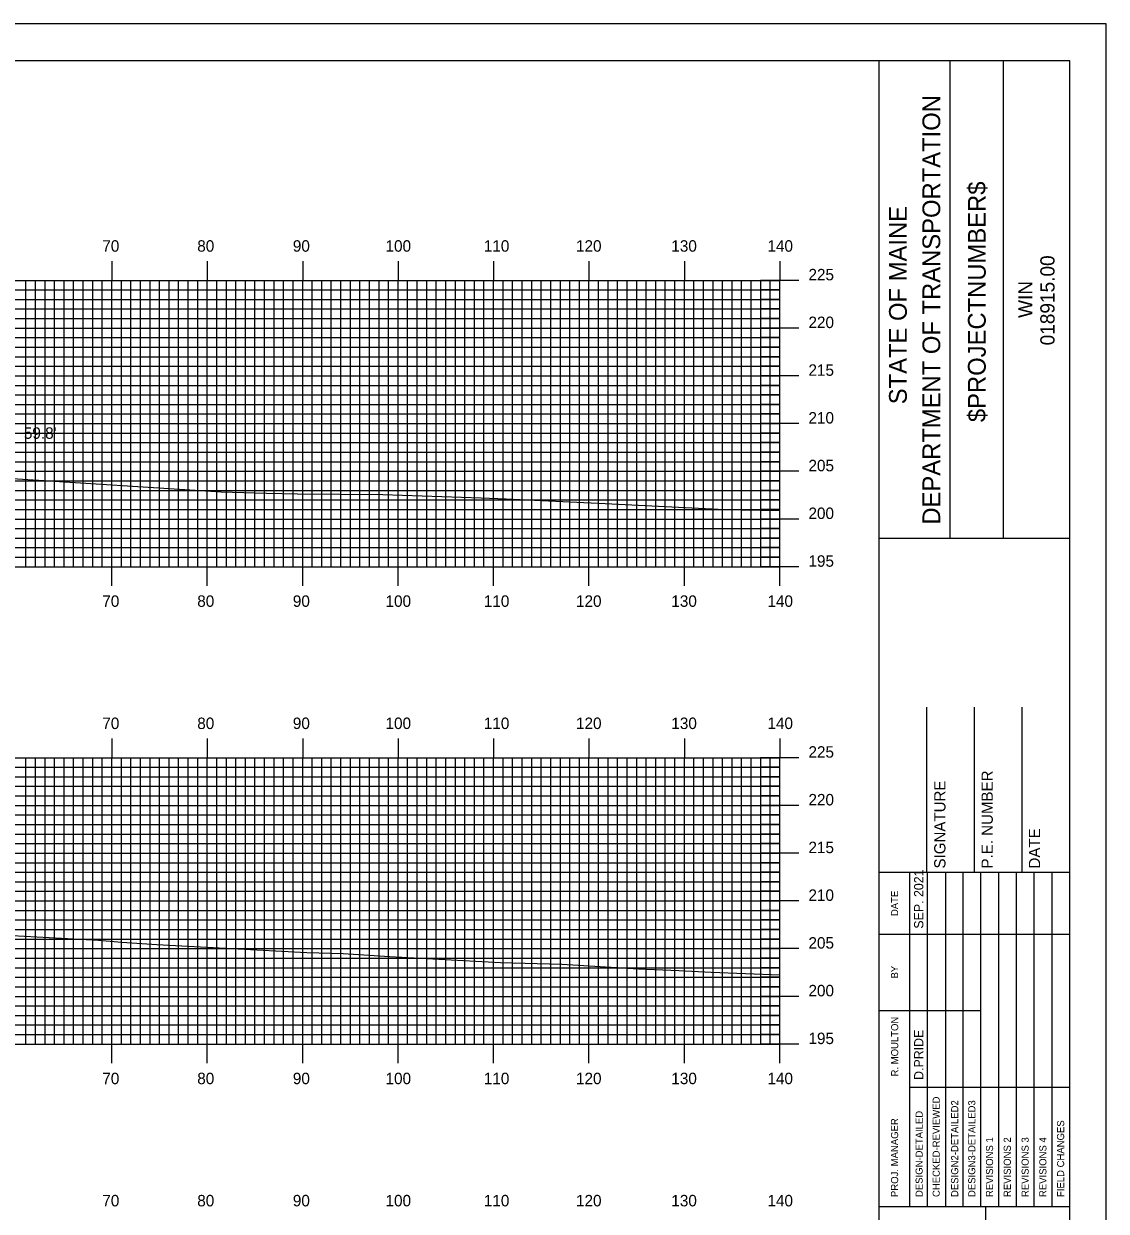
# Model space of a CAD drawing. Extents: x 1805471 to 1805814, y 442591 to 442811.
# Drawn here: x 1805697.5 to 1805810.9, y 442686.2 to 442810.5 of the extents above; entities that cross this region are included whole.
import ezdxf

# ---------------------------------------------------------------- set-up
doc = ezdxf.new("R2010")
doc.units = 0
for name, color, linetype in [('BORDER', 7, 'Continuous'), ('D_Text_Standard', 7, 'Continuous'), ('H_V ANNOTATION', 7, 'Continuous'), ('MAJOR', 7, 'Continuous'), ('MINOR', 7, 'Continuous'), ('PLOT BOUNDARY', 7, 'Continuous'), ('S_Roadway_Centerline', 7, 'Continuous')]:
    doc.layers.add(name, color=color, linetype=linetype)

msp = doc.modelspace()

# ---------------------------------------------------------------- linework, layer by layer
at = {"layer": 'BORDER'}
for p, q in [((1805787.11, 442596.67), (1805787.11, 442806.67)), ((1805794.56, 442756.66), (1805794.56, 442806.66)), ((1805800.15, 442756.66), (1805800.15, 442806.66)), ((1805787.11, 442756.65), (1805807.11, 442756.65)), ((1805792.11, 442721.67), (1805792.11, 442738.97)), ((1805797.11, 442721.67), (1805797.11, 442738.97)), ((1805802.11, 442721.67), (1805802.11, 442738.97)), ((1805787.11, 442721.67), (1805807.11, 442721.67)), ((1805787.11, 442686.67), (1805807.11, 442686.67)), ((1805798.29, 442616.67), (1805798.29, 442686.67))]:
    msp.add_line(p, q, dxfattribs=at)
msp.add_lwpolyline([(1805487.11, 442596.67), (1805807.11, 442596.67), (1805807.11, 442806.67), (1805487.11, 442806.67)], close=True, dxfattribs=at)
for points in [[(1805790.34, 442715.17), (1805790.34, 442721.67)], [(1805792.2, 442686.68), (1805792.2, 442721.67)], [(1805794.06, 442721.67), (1805794.06, 442686.68)], [(1805795.93, 442686.68), (1805795.93, 442721.67)], [(1805797.79, 442686.68), (1805797.79, 442721.67)], [(1805799.65, 442686.68), (1805799.65, 442721.67)], [(1805801.52, 442686.68), (1805801.52, 442721.67)], [(1805803.38, 442686.68), (1805803.38, 442721.67)], [(1805805.24, 442686.68), (1805805.24, 442721.67)], [(1805790.34, 442686.68), (1805790.34, 442720.26)], [(1805787.11, 442715.17), (1805807.11, 442715.17)], [(1805787.11, 442707.17), (1805790.34, 442707.17)], [(1805790.34, 442707.17), (1805797.79, 442707.17)], [(1805790.34, 442699.17), (1805807.11, 442699.17)]]:
    msp.add_lwpolyline(points, dxfattribs=at)
at = {"layer": 'MAJOR'}
for p, q in [((1805706.71, 442785.67), (1805706.71, 442783.67)), ((1805716.71, 442785.67), (1805716.71, 442783.67)), ((1805726.71, 442785.67), (1805726.71, 442783.67)), ((1805736.71, 442785.67), (1805736.71, 442783.67)), ((1805746.71, 442785.67), (1805746.71, 442783.67)), ((1805756.71, 442785.67), (1805756.71, 442783.67)), ((1805766.71, 442785.67), (1805766.71, 442783.67)), ((1805776.71, 442785.67), (1805776.71, 442783.67)), ((1805496.71, 442783.67), (1805776.71, 442783.67)), ((1805496.71, 442783.67), (1805776.71, 442783.67)), ((1805706.71, 442753.67), (1805706.71, 442783.67)), ((1805716.71, 442753.67), (1805716.71, 442783.67)), ((1805726.71, 442753.67), (1805726.71, 442783.67)), ((1805736.71, 442753.67), (1805736.71, 442783.67)), ((1805746.71, 442753.67), (1805746.71, 442783.67)), ((1805756.71, 442753.67), (1805756.71, 442783.67)), ((1805766.71, 442753.67), (1805766.71, 442783.67)), ((1805778.71, 442783.67), (1805774.7, 442783.67)), ((1805776.71, 442753.67), (1805776.71, 442783.67)), ((1805776.71, 442753.67), (1805776.71, 442783.67)), ((1805496.71, 442778.67), (1805776.71, 442778.67)), ((1805778.71, 442778.67), (1805774.7, 442778.67)), ((1805496.71, 442773.67), (1805776.71, 442773.67)), ((1805778.71, 442773.67), (1805774.7, 442773.67)), ((1805496.71, 442768.67), (1805776.71, 442768.67)), ((1805778.71, 442768.67), (1805774.7, 442768.67)), ((1805496.71, 442763.67), (1805776.71, 442763.67)), ((1805778.71, 442763.67), (1805774.7, 442763.67)), ((1805496.71, 442758.67), (1805776.71, 442758.67)), ((1805778.71, 442758.67), (1805774.7, 442758.67)), ((1805496.71, 442753.67), (1805776.71, 442753.67)), ((1805496.71, 442753.67), (1805776.71, 442753.67)), ((1805706.71, 442751.66), (1805706.71, 442753.67)), ((1805716.71, 442751.66), (1805716.71, 442753.67)), ((1805726.71, 442751.66), (1805726.71, 442753.67)), ((1805736.71, 442751.66), (1805736.71, 442753.67)), ((1805746.71, 442751.66), (1805746.71, 442753.67)), ((1805756.71, 442751.66), (1805756.71, 442753.67)), ((1805766.71, 442751.66), (1805766.71, 442753.67)), ((1805778.71, 442753.67), (1805774.7, 442753.67)), ((1805776.71, 442751.66), (1805776.71, 442753.67)), ((1805706.71, 442735.67), (1805706.71, 442733.67)), ((1805716.71, 442735.67), (1805716.71, 442733.67)), ((1805726.71, 442735.67), (1805726.71, 442733.67)), ((1805736.71, 442735.67), (1805736.71, 442733.67)), ((1805746.71, 442735.67), (1805746.71, 442733.67)), ((1805756.71, 442735.67), (1805756.71, 442733.67)), ((1805766.71, 442735.67), (1805766.71, 442733.67)), ((1805776.71, 442735.67), (1805776.71, 442733.67)), ((1805496.71, 442733.67), (1805776.71, 442733.67)), ((1805496.71, 442733.67), (1805776.71, 442733.67)), ((1805706.71, 442703.67), (1805706.71, 442733.67)), ((1805716.71, 442703.67), (1805716.71, 442733.67)), ((1805726.71, 442703.67), (1805726.71, 442733.67)), ((1805736.71, 442703.67), (1805736.71, 442733.67)), ((1805746.71, 442703.67), (1805746.71, 442733.67)), ((1805756.71, 442703.67), (1805756.71, 442733.67)), ((1805766.71, 442703.67), (1805766.71, 442733.67)), ((1805778.71, 442733.67), (1805774.7, 442733.67)), ((1805776.71, 442703.67), (1805776.71, 442733.67)), ((1805776.71, 442703.67), (1805776.71, 442733.67)), ((1805496.71, 442728.67), (1805776.71, 442728.67)), ((1805778.71, 442728.67), (1805774.7, 442728.67)), ((1805496.71, 442723.67), (1805776.71, 442723.67)), ((1805778.71, 442723.67), (1805774.7, 442723.67)), ((1805496.71, 442718.67), (1805776.71, 442718.67)), ((1805778.71, 442718.67), (1805774.7, 442718.67)), ((1805496.71, 442713.67), (1805776.71, 442713.67)), ((1805778.71, 442713.67), (1805774.7, 442713.67)), ((1805496.71, 442708.67), (1805776.71, 442708.67)), ((1805778.71, 442708.67), (1805774.7, 442708.67)), ((1805496.71, 442703.67), (1805776.71, 442703.67)), ((1805496.71, 442703.67), (1805776.71, 442703.67)), ((1805706.71, 442701.66), (1805706.71, 442703.67)), ((1805716.71, 442701.66), (1805716.71, 442703.67)), ((1805726.71, 442701.66), (1805726.71, 442703.67)), ((1805736.71, 442701.66), (1805736.71, 442703.67)), ((1805746.71, 442701.66), (1805746.71, 442703.67)), ((1805756.71, 442701.66), (1805756.71, 442703.67)), ((1805766.71, 442701.66), (1805766.71, 442703.67)), ((1805778.71, 442703.67), (1805774.7, 442703.67)), ((1805776.71, 442701.66), (1805776.71, 442703.67))]:
    msp.add_line(p, q, dxfattribs=at)
at = {"layer": 'MINOR'}
for p, q in [((1805697.71, 442753.67), (1805697.71, 442783.67)), ((1805698.71, 442753.67), (1805698.71, 442783.67)), ((1805699.71, 442753.67), (1805699.71, 442783.67)), ((1805700.71, 442753.67), (1805700.71, 442783.67)), ((1805701.71, 442753.67), (1805701.71, 442783.67)), ((1805702.71, 442753.67), (1805702.71, 442783.67)), ((1805703.71, 442753.67), (1805703.71, 442783.67)), ((1805704.71, 442753.67), (1805704.71, 442783.67)), ((1805705.71, 442753.67), (1805705.71, 442783.67)), ((1805707.71, 442753.67), (1805707.71, 442783.67)), ((1805708.71, 442753.67), (1805708.71, 442783.67)), ((1805709.71, 442753.67), (1805709.71, 442783.67)), ((1805710.71, 442753.67), (1805710.71, 442783.67)), ((1805711.71, 442753.67), (1805711.71, 442783.67)), ((1805712.71, 442753.67), (1805712.71, 442783.67)), ((1805713.71, 442753.67), (1805713.71, 442783.67)), ((1805714.71, 442753.67), (1805714.71, 442783.67)), ((1805715.71, 442753.67), (1805715.71, 442783.67)), ((1805717.71, 442753.67), (1805717.71, 442783.67)), ((1805718.71, 442753.67), (1805718.71, 442783.67)), ((1805719.71, 442753.67), (1805719.71, 442783.67)), ((1805720.71, 442753.67), (1805720.71, 442783.67)), ((1805721.71, 442753.67), (1805721.71, 442783.67)), ((1805722.71, 442753.67), (1805722.71, 442783.67)), ((1805723.71, 442753.67), (1805723.71, 442783.67)), ((1805724.71, 442753.67), (1805724.71, 442783.67)), ((1805725.71, 442753.67), (1805725.71, 442783.67)), ((1805727.71, 442753.67), (1805727.71, 442783.67)), ((1805728.71, 442753.67), (1805728.71, 442783.67)), ((1805729.71, 442753.67), (1805729.71, 442783.67)), ((1805730.71, 442753.67), (1805730.71, 442783.67)), ((1805731.71, 442753.67), (1805731.71, 442783.67)), ((1805732.71, 442753.67), (1805732.71, 442783.67)), ((1805733.71, 442753.67), (1805733.71, 442783.67)), ((1805734.71, 442753.67), (1805734.71, 442783.67)), ((1805735.71, 442753.67), (1805735.71, 442783.67)), ((1805737.71, 442753.67), (1805737.71, 442783.67)), ((1805738.71, 442753.67), (1805738.71, 442783.67)), ((1805739.71, 442753.67), (1805739.71, 442783.67)), ((1805740.71, 442753.67), (1805740.71, 442783.67)), ((1805741.71, 442753.67), (1805741.71, 442783.67)), ((1805742.71, 442753.67), (1805742.71, 442783.67)), ((1805743.71, 442753.67), (1805743.71, 442783.67)), ((1805744.71, 442753.67), (1805744.71, 442783.67)), ((1805745.71, 442753.67), (1805745.71, 442783.67)), ((1805747.71, 442753.67), (1805747.71, 442783.67)), ((1805748.71, 442753.67), (1805748.71, 442783.67)), ((1805749.71, 442753.67), (1805749.71, 442783.67)), ((1805750.71, 442753.67), (1805750.71, 442783.67)), ((1805751.71, 442753.67), (1805751.71, 442783.67)), ((1805752.71, 442753.67), (1805752.71, 442783.67)), ((1805753.71, 442753.67), (1805753.71, 442783.67)), ((1805754.71, 442753.67), (1805754.71, 442783.67)), ((1805755.71, 442753.67), (1805755.71, 442783.67)), ((1805757.71, 442753.67), (1805757.71, 442783.67)), ((1805758.71, 442753.67), (1805758.71, 442783.67)), ((1805759.71, 442753.67), (1805759.71, 442783.67)), ((1805760.71, 442753.67), (1805760.71, 442783.67)), ((1805761.71, 442753.67), (1805761.71, 442783.67)), ((1805762.71, 442753.67), (1805762.71, 442783.67)), ((1805763.71, 442753.67), (1805763.71, 442783.67)), ((1805764.71, 442753.67), (1805764.71, 442783.67)), ((1805765.71, 442753.67), (1805765.71, 442783.67)), ((1805767.71, 442753.67), (1805767.71, 442783.67)), ((1805768.71, 442753.67), (1805768.71, 442783.67)), ((1805769.71, 442753.67), (1805769.71, 442783.67)), ((1805770.71, 442753.67), (1805770.71, 442783.67)), ((1805771.71, 442753.67), (1805771.71, 442783.67)), ((1805772.71, 442753.67), (1805772.71, 442783.67)), ((1805773.71, 442753.67), (1805773.71, 442783.67)), ((1805774.71, 442753.67), (1805774.71, 442783.67)), ((1805775.71, 442753.67), (1805775.71, 442783.67)), ((1805496.71, 442782.67), (1805776.71, 442782.67)), ((1805776.71, 442782.67), (1805774.7, 442782.67)), ((1805496.71, 442781.67), (1805776.71, 442781.67)), ((1805776.71, 442781.67), (1805774.7, 442781.67)), ((1805496.71, 442780.67), (1805776.71, 442780.67)), ((1805776.71, 442780.67), (1805774.7, 442780.67)), ((1805496.71, 442779.67), (1805776.71, 442779.67)), ((1805776.71, 442779.67), (1805774.7, 442779.67)), ((1805496.71, 442777.67), (1805776.71, 442777.67)), ((1805776.71, 442777.67), (1805774.7, 442777.67)), ((1805496.71, 442776.67), (1805776.71, 442776.67)), ((1805776.71, 442776.67), (1805774.7, 442776.67)), ((1805496.71, 442775.67), (1805776.71, 442775.67)), ((1805776.71, 442775.67), (1805774.7, 442775.67)), ((1805496.71, 442774.67), (1805776.71, 442774.67)), ((1805776.71, 442774.67), (1805774.7, 442774.67)), ((1805496.71, 442772.67), (1805776.71, 442772.67)), ((1805776.71, 442772.67), (1805774.7, 442772.67)), ((1805496.71, 442771.67), (1805776.71, 442771.67)), ((1805776.71, 442771.67), (1805774.7, 442771.67)), ((1805496.71, 442770.67), (1805776.71, 442770.67)), ((1805776.71, 442770.67), (1805774.7, 442770.67)), ((1805496.71, 442769.67), (1805776.71, 442769.67)), ((1805776.71, 442769.67), (1805774.7, 442769.67)), ((1805496.71, 442767.67), (1805776.71, 442767.67)), ((1805776.71, 442767.67), (1805774.7, 442767.67)), ((1805496.71, 442766.67), (1805776.71, 442766.67)), ((1805776.71, 442766.67), (1805774.7, 442766.67)), ((1805496.71, 442765.67), (1805776.71, 442765.67)), ((1805776.71, 442765.67), (1805774.7, 442765.67)), ((1805496.71, 442764.67), (1805776.71, 442764.67)), ((1805776.71, 442764.67), (1805774.7, 442764.67)), ((1805496.71, 442762.67), (1805776.71, 442762.67)), ((1805776.71, 442762.67), (1805774.7, 442762.67)), ((1805496.71, 442761.67), (1805776.71, 442761.67)), ((1805776.71, 442761.67), (1805774.7, 442761.67)), ((1805496.71, 442760.67), (1805776.71, 442760.67)), ((1805776.71, 442760.67), (1805774.7, 442760.67)), ((1805496.71, 442759.67), (1805776.71, 442759.67)), ((1805776.71, 442759.67), (1805774.7, 442759.67)), ((1805496.71, 442757.67), (1805776.71, 442757.67)), ((1805776.71, 442757.67), (1805774.7, 442757.67)), ((1805496.71, 442756.67), (1805776.71, 442756.67)), ((1805776.71, 442756.67), (1805774.7, 442756.67)), ((1805496.71, 442755.67), (1805776.71, 442755.67)), ((1805776.71, 442755.67), (1805774.7, 442755.67)), ((1805496.71, 442754.67), (1805776.71, 442754.67)), ((1805776.71, 442754.67), (1805774.7, 442754.67)), ((1805496.71, 442732.67), (1805776.71, 442732.67)), ((1805697.71, 442703.67), (1805697.71, 442733.67)), ((1805698.71, 442703.67), (1805698.71, 442733.67)), ((1805699.71, 442703.67), (1805699.71, 442733.67)), ((1805700.71, 442703.67), (1805700.71, 442733.67)), ((1805701.71, 442703.67), (1805701.71, 442733.67)), ((1805702.71, 442703.67), (1805702.71, 442733.67)), ((1805703.71, 442703.67), (1805703.71, 442733.67)), ((1805704.71, 442703.67), (1805704.71, 442733.67)), ((1805705.71, 442703.67), (1805705.71, 442733.67)), ((1805707.71, 442703.67), (1805707.71, 442733.67)), ((1805708.71, 442703.67), (1805708.71, 442733.67)), ((1805709.71, 442703.67), (1805709.71, 442733.67)), ((1805710.71, 442703.67), (1805710.71, 442733.67)), ((1805711.71, 442703.67), (1805711.71, 442733.67)), ((1805712.71, 442703.67), (1805712.71, 442733.67)), ((1805713.71, 442703.67), (1805713.71, 442733.67)), ((1805714.71, 442703.67), (1805714.71, 442733.67)), ((1805715.71, 442703.67), (1805715.71, 442733.67)), ((1805717.71, 442703.67), (1805717.71, 442733.67)), ((1805718.71, 442703.67), (1805718.71, 442733.67)), ((1805719.71, 442703.67), (1805719.71, 442733.67)), ((1805720.71, 442703.67), (1805720.71, 442733.67)), ((1805721.71, 442703.67), (1805721.71, 442733.67)), ((1805722.71, 442703.67), (1805722.71, 442733.67)), ((1805723.71, 442703.67), (1805723.71, 442733.67)), ((1805724.71, 442703.67), (1805724.71, 442733.67)), ((1805725.71, 442703.67), (1805725.71, 442733.67)), ((1805727.71, 442703.67), (1805727.71, 442733.67)), ((1805728.71, 442703.67), (1805728.71, 442733.67)), ((1805729.71, 442703.67), (1805729.71, 442733.67)), ((1805730.71, 442703.67), (1805730.71, 442733.67)), ((1805731.71, 442703.67), (1805731.71, 442733.67)), ((1805732.71, 442703.67), (1805732.71, 442733.67)), ((1805733.71, 442703.67), (1805733.71, 442733.67)), ((1805734.71, 442703.67), (1805734.71, 442733.67)), ((1805735.71, 442703.67), (1805735.71, 442733.67)), ((1805737.71, 442703.67), (1805737.71, 442733.67)), ((1805738.71, 442703.67), (1805738.71, 442733.67)), ((1805739.71, 442703.67), (1805739.71, 442733.67)), ((1805740.71, 442703.67), (1805740.71, 442733.67)), ((1805741.71, 442703.67), (1805741.71, 442733.67)), ((1805742.71, 442703.67), (1805742.71, 442733.67)), ((1805743.71, 442703.67), (1805743.71, 442733.67)), ((1805744.71, 442703.67), (1805744.71, 442733.67)), ((1805745.71, 442703.67), (1805745.71, 442733.67)), ((1805747.71, 442703.67), (1805747.71, 442733.67)), ((1805748.71, 442703.67), (1805748.71, 442733.67)), ((1805749.71, 442703.67), (1805749.71, 442733.67)), ((1805750.71, 442703.67), (1805750.71, 442733.67)), ((1805751.71, 442703.67), (1805751.71, 442733.67)), ((1805752.71, 442703.67), (1805752.71, 442733.67)), ((1805753.71, 442703.67), (1805753.71, 442733.67)), ((1805754.71, 442703.67), (1805754.71, 442733.67)), ((1805755.71, 442703.67), (1805755.71, 442733.67)), ((1805757.71, 442703.67), (1805757.71, 442733.67)), ((1805758.71, 442703.67), (1805758.71, 442733.67)), ((1805759.71, 442703.67), (1805759.71, 442733.67)), ((1805760.71, 442703.67), (1805760.71, 442733.67)), ((1805761.71, 442703.67), (1805761.71, 442733.67)), ((1805762.71, 442703.67), (1805762.71, 442733.67)), ((1805763.71, 442703.67), (1805763.71, 442733.67)), ((1805764.71, 442703.67), (1805764.71, 442733.67)), ((1805765.71, 442703.67), (1805765.71, 442733.67)), ((1805767.71, 442703.67), (1805767.71, 442733.67)), ((1805768.71, 442703.67), (1805768.71, 442733.67)), ((1805769.71, 442703.67), (1805769.71, 442733.67)), ((1805770.71, 442703.67), (1805770.71, 442733.67)), ((1805771.71, 442703.67), (1805771.71, 442733.67)), ((1805772.71, 442703.67), (1805772.71, 442733.67)), ((1805773.71, 442703.67), (1805773.71, 442733.67)), ((1805776.71, 442732.67), (1805774.7, 442732.67)), ((1805774.71, 442703.67), (1805774.71, 442733.67)), ((1805775.71, 442703.67), (1805775.71, 442733.67)), ((1805496.71, 442731.67), (1805776.71, 442731.67)), ((1805776.71, 442731.67), (1805774.7, 442731.67)), ((1805496.71, 442730.67), (1805776.71, 442730.67)), ((1805776.71, 442730.67), (1805774.7, 442730.67)), ((1805496.71, 442729.67), (1805776.71, 442729.67)), ((1805776.71, 442729.67), (1805774.7, 442729.67)), ((1805496.71, 442727.67), (1805776.71, 442727.67)), ((1805776.71, 442727.67), (1805774.7, 442727.67)), ((1805496.71, 442726.67), (1805776.71, 442726.67)), ((1805776.71, 442726.67), (1805774.7, 442726.67)), ((1805496.71, 442725.67), (1805776.71, 442725.67)), ((1805776.71, 442725.67), (1805774.7, 442725.67)), ((1805496.71, 442724.67), (1805776.71, 442724.67)), ((1805776.71, 442724.67), (1805774.7, 442724.67)), ((1805496.71, 442722.67), (1805776.71, 442722.67)), ((1805776.71, 442722.67), (1805774.7, 442722.67)), ((1805496.71, 442721.67), (1805776.71, 442721.67)), ((1805776.71, 442721.67), (1805774.7, 442721.67)), ((1805496.71, 442720.67), (1805776.71, 442720.67)), ((1805776.71, 442720.67), (1805774.7, 442720.67)), ((1805496.71, 442719.67), (1805776.71, 442719.67)), ((1805776.71, 442719.67), (1805774.7, 442719.67)), ((1805496.71, 442717.67), (1805776.71, 442717.67)), ((1805776.71, 442717.67), (1805774.7, 442717.67)), ((1805496.71, 442716.67), (1805776.71, 442716.67)), ((1805776.71, 442716.67), (1805774.7, 442716.67)), ((1805496.71, 442715.67), (1805776.71, 442715.67)), ((1805776.71, 442715.67), (1805774.7, 442715.67)), ((1805496.71, 442714.67), (1805776.71, 442714.67)), ((1805776.71, 442714.67), (1805774.7, 442714.67)), ((1805496.71, 442712.67), (1805776.71, 442712.67)), ((1805776.71, 442712.67), (1805774.7, 442712.67)), ((1805496.71, 442711.67), (1805776.71, 442711.67)), ((1805776.71, 442711.67), (1805774.7, 442711.67)), ((1805496.71, 442710.67), (1805776.71, 442710.67)), ((1805776.71, 442710.67), (1805774.7, 442710.67)), ((1805496.71, 442709.67), (1805776.71, 442709.67)), ((1805776.71, 442709.67), (1805774.7, 442709.67)), ((1805496.71, 442707.67), (1805776.71, 442707.67)), ((1805496.71, 442706.67), (1805776.71, 442706.67)), ((1805776.71, 442707.67), (1805774.7, 442707.67)), ((1805776.71, 442706.67), (1805774.7, 442706.67)), ((1805496.71, 442705.67), (1805776.71, 442705.67)), ((1805776.71, 442705.67), (1805774.7, 442705.67)), ((1805496.71, 442704.67), (1805776.71, 442704.67)), ((1805776.71, 442704.67), (1805774.7, 442704.67))]:
    msp.add_line(p, q, dxfattribs=at)
at = {"layer": 'PLOT BOUNDARY'}
msp.add_lwpolyline([(1805470.92, 442590.55), (1805810.92, 442590.55), (1805810.92, 442810.55), (1805470.92, 442810.55)], close=True, dxfattribs=at)
at = {"layer": 'S_Roadway_Centerline'}
for points in [[(1805694.58, 442763.03), (1805705.07, 442762.34), (1805718.18, 442761.53), (1805722.93, 442761.38), (1805726.17, 442761.32), (1805735.1, 442761.25), (1805745.43, 442760.88), (1805748.03, 442760.77), (1805758.42, 442760.31), (1805769.58, 442759.75), (1805770.96, 442759.68), (1805772.68, 442759.63), (1805776.71, 442759.56)], [(1805696.25, 442715.04), (1805705.33, 442714.54), (1805707.75, 442714.33), (1805711.44, 442714.09), (1805727.16, 442713.25), (1805730.94, 442713.15), (1805735.82, 442712.86), (1805747.45, 442712.21), (1805753.86, 442712.03), (1805761.9, 442711.55), (1805766.13, 442711.36), (1805769.51, 442711.21), (1805776.71, 442710.91)]]:
    msp.add_lwpolyline(points, dxfattribs=at)

# ---------------------------------------------------------------- texts
at = {"layer": 'BORDER'}
for s, height, p in [('DEPARTMENT OF TRANSPORTATION', 1.8635, (1805793.52, 442758.08)), ('$PROJECTNUMBER$', 1.8635, (1805798.29, 442768.82)), ('STATE OF MAINE', 1.8635, (1805790.02, 442770.69)), ('018915.00', 1.491, (1805805.5, 442776.86)), ('WIN', 1.491, (1805803.18, 442779.73)), ('P.E. NUMBER', 1.1811, (1805799.03, 442722.06)), ('SIGNATURE', 1.181, (1805794.07, 442722.06)), ('DATE', 1.181, (1805803.99, 442722.06)), ('SEP. 2021', 0.969, (1805791.75, 442715.76)), ('DATE', 0.743, (1805789.11, 442717.08)), ('BY', 0.743, (1805789.11, 442710.54)), ('R. MOULTON', 0.745, (1805789.12, 442700.28)), ('D.PRIDE', 0.969, (1805791.75, 442699.92)), ('CHECKED-REVIEWED', 0.7455, (1805793.47, 442687.65)), ('DESIGN2-DETAILED2', 0.7455, (1805795.41, 442687.65)), ('DESIGN3-DETAILED3', 0.7455, (1805797.2, 442687.65)), ('DESIGN-DETAILED', 0.7455, (1805791.68, 442687.65)), ('PROJ. MANAGER', 0.7455, (1805789.11, 442687.65)), ('FIELD CHANGES', 0.7455, (1805806.51, 442687.65)), ('REVISIONS 1', 0.7455, (1805799.06, 442687.65)), ('REVISIONS 2', 0.7455, (1805800.92, 442687.65)), ('REVISIONS 3', 0.7455, (1805802.79, 442687.65)), ('REVISIONS 4', 0.7455, (1805804.65, 442687.65))]:
    msp.add_text(s, height=height, rotation=90, dxfattribs=at).set_placement(p)
at = {"layer": 'D_Text_Standard'}
msp.add_text("59.8'", height=1.2, dxfattribs=at).set_placement((1805697.49, 442767.07))
at = {"layer": 'H_V ANNOTATION'}
for s, p in [('70', (1805705.71, 442786.67)), ('80', (1805715.66, 442786.67)), ('90', (1805725.68, 442786.67)), ('100', (1805735.39, 442786.67)), ('110', (1805745.69, 442786.67)), ('120', (1805755.35, 442786.67)), ('130', (1805765.34, 442786.67)), ('140', (1805775.41, 442786.67)), ('225', (1805779.71, 442783.67)), ('220', (1805779.71, 442778.67)), ('215', (1805779.71, 442773.67)), ('210', (1805779.71, 442768.67)), ('205', (1805779.71, 442763.67)), ('200', (1805779.71, 442758.67)), ('195', (1805779.71, 442753.67)), ('70', (1805705.71, 442749.47)), ('80', (1805715.66, 442749.47)), ('90', (1805725.68, 442749.47)), ('100', (1805735.39, 442749.47)), ('110', (1805745.69, 442749.47)), ('120', (1805755.35, 442749.47)), ('130', (1805765.34, 442749.47)), ('140', (1805775.41, 442749.47)), ('70', (1805705.71, 442736.67)), ('80', (1805715.66, 442736.67)), ('90', (1805725.68, 442736.67)), ('100', (1805735.39, 442736.67)), ('110', (1805745.69, 442736.67)), ('120', (1805755.35, 442736.67)), ('130', (1805765.34, 442736.67)), ('140', (1805775.41, 442736.67)), ('225', (1805779.71, 442733.67)), ('220', (1805779.71, 442728.67)), ('215', (1805779.71, 442723.67)), ('210', (1805779.71, 442718.67)), ('205', (1805779.71, 442713.67)), ('200', (1805779.71, 442708.67)), ('195', (1805779.71, 442703.67)), ('70', (1805705.71, 442699.47)), ('80', (1805715.66, 442699.47)), ('90', (1805725.68, 442699.47)), ('100', (1805735.39, 442699.47)), ('110', (1805745.69, 442699.47)), ('120', (1805755.35, 442699.47)), ('130', (1805765.34, 442699.47)), ('140', (1805775.41, 442699.47)), ('70', (1805705.71, 442686.67)), ('80', (1805715.66, 442686.67)), ('90', (1805725.68, 442686.67)), ('100', (1805735.39, 442686.67)), ('110', (1805745.69, 442686.67)), ('120', (1805755.35, 442686.67)), ('130', (1805765.34, 442686.67)), ('140', (1805775.41, 442686.67))]:
    msp.add_text(s, height=1.2, dxfattribs=at).set_placement(p)

doc.saveas('drawing.dxf')
